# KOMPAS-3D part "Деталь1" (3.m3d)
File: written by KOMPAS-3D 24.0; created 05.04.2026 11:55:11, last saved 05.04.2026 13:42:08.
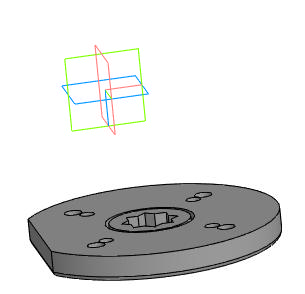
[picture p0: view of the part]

Document properties: Автор: R2D2; Полное имя файла: E:\Работа\Зайцев\Аксессуары для пневмоприводов\Ручной дублер DN.ru\MON4-1200-T54-ISO Ручной дублер DN.ru\исходные материалы\3.m3d

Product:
- Body: Тело 2  | qty 1
    Масса: 1.998139
- Part/product: Деталь1
    Масса: 35.407781
    additional columns: Типовые

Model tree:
1. Операция без истории:1
2. Эскиз:1  (with: Грань.Операция без истории:1, Ребро.Операция без истории:1)
3. Элемент выдавливания:1  (with: Грань.Операция без истории:1)
     Расстояние 1 = -20.8
4. Скругление:1  (with: Ребро.Элемент выдавливания:1)
     Радиус = 3
5. Эскиз:2  (with: Ребро.Скругление:1)
6. Элемент выдавливания:3
     Расстояние 1 = 500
